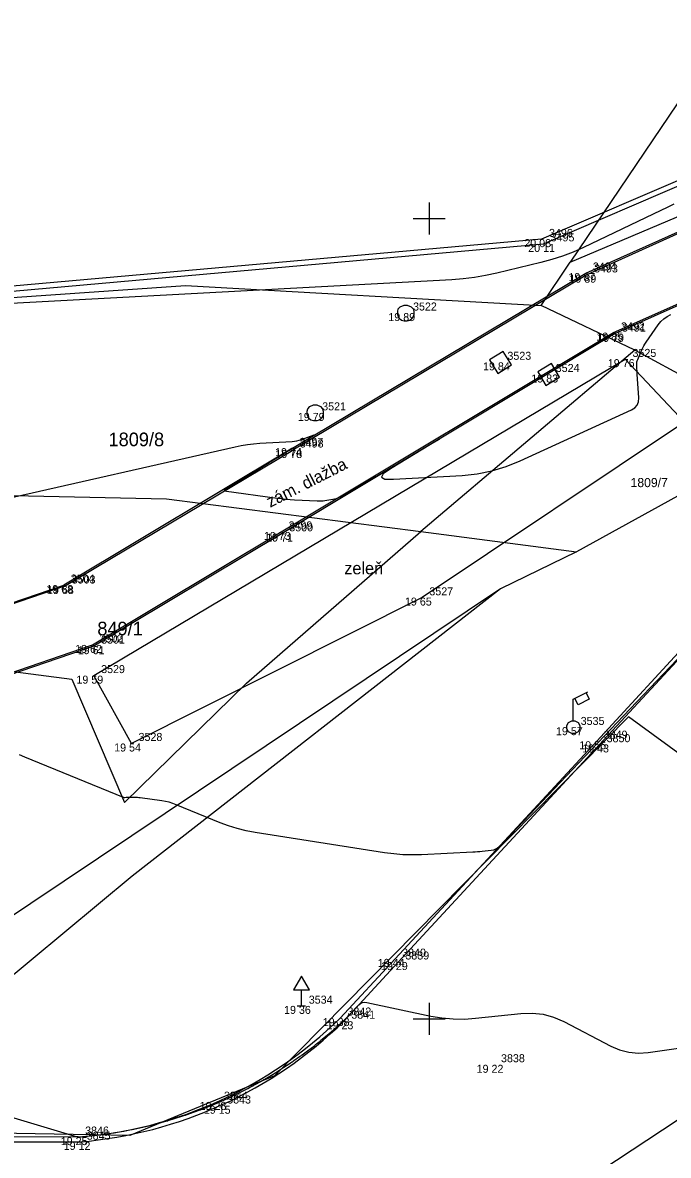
# Model space of a CAD drawing. Extents: x -702257 to -701487, y -1009871 to -1008841.
# Drawn here: x -702162.7 to -702142.52, y -1009729.27 to -1009693.87 of the extents above; entities that cross this region are included whole.
import ezdxf

# ---------------------------------------------------------------- set-up
doc = ezdxf.new("R2010")
doc.units = 0
for name, color, linetype in [('Ex_Major Contours', 7, 'Continuous'), ('Ex_Minor Contours', 7, 'Continuous'), ('Z_body', 7, 'Continuous'), ('Z_body_cisla', 7, 'Continuous'), ('Z_body_vysky_redukovane', 7, 'Continuous'), ('Z_dopravni_znacky', 7, 'Continuous'), ('Z_hektometricka_sit', 7, 'Continuous'), ('Z_katastr_cisla_pozemkova', 7, 'Continuous'), ('Z_katastr_hranice', 7, 'Continuous'), ('Z_komunikace', 7, 'Continuous'), ('Z_obruba', 7, 'Continuous'), ('Z_popisy', 7, 'Continuous'), ('Z_site_kanalizace_znaky', 7, 'Continuous'), ('Z_site_nerozlisene_znaky', 7, 'Continuous'), ('Z_site_vo_znaky', 7, 'Continuous'), ('Z_zelen_obvod', 7, 'Continuous')]:
    doc.layers.add(name, color=color, linetype=linetype)

# ---------------------------------------------------------------- blocks, each defined once
blk = doc.blocks.new('POINT_DISPLAY')
blk.add_line((0, 0), (0, 0))
blk = doc.blocks.new('Z620')
for p, q in [((-0.25, 0.05), (-0.23, 0.13)), ((-0.25, -0.05), (-0.25, 0.05)), ((-0.23, 0.13), (-0.17, 0.2)), ((-0.17, 0.2), (-0.05, 0.25)), ((-0.05, 0.25), (0.05, 0.25)), ((0.05, 0.25), (0.17, 0.2)), ((0.17, 0.2), (0.23, 0.13)), ((0.23, 0.13), (0.25, 0.05)), ((0.25, 0.05), (0.25, -0.05)), ((-0.2, -0.17), (-0.25, -0.05)), ((-0.13, -0.23), (-0.2, -0.17)), ((-0.05, -0.25), (-0.13, -0.23)), ((0.05, -0.25), (-0.05, -0.25)), ((0.13, -0.23), (0.05, -0.25)), ((0.2, -0.17), (0.13, -0.23)), ((0.25, -0.05), (0.2, -0.17))]:
    blk.add_line(p, q)
blk = doc.blocks.new('Z13')
for p, q in [((0, 0.88), (0.45, 1.1)), ((0.4, 1.07), (0.5, 0.88)), ((0, 0.2), (0, 0.88)), ((0.15, 0.7), (0.05, 0.9)), ((0.5, 0.88), (0.15, 0.7)), ((-0.2, 0.05), (-0.15, 0.15)), ((-0.2, -0.05), (-0.2, 0.05)), ((-0.15, 0.15), (-0.05, 0.2)), ((-0.05, 0.2), (0.05, 0.2)), ((0.05, 0.2), (0.15, 0.15)), ((0.15, 0.15), (0.2, 0.05)), ((0.2, 0.05), (0.2, -0.05)), ((-0.15, -0.15), (-0.2, -0.05)), ((-0.05, -0.2), (-0.15, -0.15)), ((0.05, -0.2), (-0.05, -0.2)), ((0.15, -0.15), (0.05, -0.2)), ((0.2, -0.05), (0.15, -0.15))]:
    blk.add_line(p, q)
blk = doc.blocks.new('Z608')
for p, q in [((0.25, 0.25), (-0.25, 0.25)), ((-0.25, 0.25), (-0.25, -0.25)), ((0.25, -0.25), (0.25, 0.25)), ((-0.25, -0.25), (0.25, -0.25))]:
    blk.add_line(p, q)
blk = doc.blocks.new('Z527')
for p, q in [((0, 0.93), (-0.25, 0.5)), ((0.25, 0.5), (0, 0.93)), ((-0.25, 0.5), (0.25, 0.5)), ((0, 0), (0, 0.5)), ((-0.13, 0), (0.13, 0))]:
    blk.add_line(p, q)

msp = doc.modelspace()

# ---------------------------------------------------------------- linework, layer by layer
at = {"layer": 'Ex_Major Contours'}
msp.add_lwpolyline([(-702142.349, -1009699.552), (-702142.555, -1009699.647), (-702142.759, -1009699.744), (-702145.175, -1009700.901), (-702145.498, -1009701.045), (-702145.827, -1009701.172), (-702146.163, -1009701.281), (-702146.505, -1009701.373), (-702147.885, -1009701.704), (-702148.231, -1009701.779), (-702148.58, -1009701.838), (-702148.93, -1009701.881), (-702149.284, -1009701.908), (-702165.593, -1009702.79)], dxfattribs=at)
at = {"layer": 'Ex_Minor Contours'}
for points in [[(-702163.525, -1009708.813), (-702156.058, -1009707.129), (-702155.868, -1009707.09), (-702155.677, -1009707.059), (-702155.485, -1009707.036), (-702155.291, -1009707.02), (-702154.277, -1009706.959), (-702154.203, -1009706.952), (-702154.13, -1009706.94), (-702154.058, -1009706.922), (-702153.987, -1009706.9), (-702153.59, -1009706.758), (-702153.581, -1009706.755), (-702153.577, -1009706.755), (-702153.579, -1009706.758), (-702153.588, -1009706.764), (-702153.634, -1009706.794), (-702153.657, -1009706.809), (-702153.68, -1009706.823), (-702154.115, -1009707.091), (-702154.191, -1009707.138), (-702154.268, -1009707.185), (-702154.344, -1009707.232), (-702154.42, -1009707.279), (-702156.406, -1009708.495), (-702156.407, -1009708.496), (-702156.407, -1009708.498), (-702156.403, -1009708.504), (-702156.401, -1009708.505), (-702156.399, -1009708.505), (-702154.749, -1009708.729), (-702154.613, -1009708.746), (-702154.475, -1009708.761), (-702154.338, -1009708.772), (-702154.201, -1009708.781), (-702153.497, -1009708.82), (-702153.436, -1009708.821), (-702153.375, -1009708.82), (-702153.314, -1009708.815), (-702153.253, -1009708.808), (-702153.01, -1009708.77), (-702152.95, -1009708.758), (-702152.892, -1009708.741), (-702152.836, -1009708.719), (-702152.781, -1009708.691), (-702151.945, -1009708.222), (-702151.788, -1009708.133), (-702151.631, -1009708.044), (-702151.475, -1009707.953), (-702151.32, -1009707.862), (-702149.954, -1009707.051), (-702149.744, -1009706.927), (-702149.674, -1009706.887), (-702149.743, -1009706.93), (-702149.951, -1009707.056), (-702151.209, -1009707.818), (-702151.429, -1009707.975), (-702151.486, -1009708.082), (-702151.379, -1009708.138), (-702151.108, -1009708.143), (-702148.965, -1009708.022), (-702148.496, -1009707.973), (-702148.037, -1009707.882), (-702147.589, -1009707.748), (-702147.151, -1009707.571), (-702143.672, -1009705.976), (-702143.566, -1009705.91), (-702143.493, -1009705.824), (-702143.452, -1009705.719), (-702143.444, -1009705.594), (-702143.493, -1009704.861), (-702143.495, -1009704.823), (-702143.497, -1009704.784), (-702143.499, -1009704.745), (-702143.501, -1009704.707), (-702143.506, -1009704.552), (-702143.505, -1009704.514), (-702143.5, -1009704.477), (-702143.491, -1009704.44), (-702143.478, -1009704.404), (-702143.345, -1009704.098), (-702143.316, -1009704.036), (-702143.284, -1009703.976), (-702143.25, -1009703.917), (-702143.212, -1009703.86), (-702142.837, -1009703.316), (-702142.755, -1009703.214), (-702142.662, -1009703.126), (-702142.557, -1009703.052), (-702142.441, -1009702.993)], [(-702140.79, -1009712.24), (-702143.921, -1009715.537), (-702144.32, -1009715.956), (-702144.719, -1009716.376), (-702145.117, -1009716.795), (-702145.516, -1009717.215), (-702147.81, -1009719.625), (-702147.863, -1009719.672), (-702147.921, -1009719.707), (-702147.985, -1009719.732), (-702148.055, -1009719.745), (-702148.344, -1009719.774), (-702148.417, -1009719.781), (-702148.489, -1009719.787), (-702148.562, -1009719.792), (-702148.635, -1009719.796), (-702150.235, -1009719.875), (-702150.526, -1009719.882), (-702150.816, -1009719.875), (-702151.105, -1009719.852), (-702151.393, -1009719.814), (-702155.439, -1009719.18), (-702155.719, -1009719.128), (-702155.995, -1009719.06), (-702156.266, -1009718.975), (-702156.533, -1009718.875), (-702157.902, -1009718.312), (-702158.012, -1009718.271), (-702158.124, -1009718.237), (-702158.238, -1009718.21), (-702158.354, -1009718.191), (-702159.033, -1009718.1), (-702159.054, -1009718.097), (-702159.075, -1009718.095), (-702159.118, -1009718.091), (-702159.128, -1009718.09), (-702159.138, -1009718.089), (-702159.148, -1009718.088), (-702159.158, -1009718.088), (-702159.199, -1009718.085), (-702159.219, -1009718.084), (-702159.239, -1009718.084), (-702159.278, -1009718.083), (-702159.298, -1009718.083), (-702159.317, -1009718.083), (-702159.356, -1009718.084), (-702159.376, -1009718.084), (-702159.395, -1009718.085), (-702159.434, -1009718.088), (-702159.453, -1009718.089), (-702159.472, -1009718.091), (-702159.511, -1009718.095), (-702159.521, -1009718.095), (-702159.53, -1009718.094), (-702159.539, -1009718.092), (-702159.548, -1009718.089), (-702162.631, -1009716.824), (-702162.806, -1009716.754)], [(-702165.149, -1009727.447), (-702161.105, -1009728.659), (-702161.037, -1009728.676), (-702160.969, -1009728.686), (-702160.899, -1009728.69), (-702160.83, -1009728.686), (-702160.408, -1009728.644), (-702159.85, -1009728.566), (-702159.844, -1009728.565), (-702159.299, -1009728.466), (-702159.279, -1009728.462), (-702158.758, -1009728.344), (-702158.725, -1009728.337), (-702158.715, -1009728.334), (-702158.223, -1009728.202), (-702158.2, -1009728.195), (-702158.17, -1009728.187), (-702158.158, -1009728.184), (-702158.152, -1009728.182), (-702157.698, -1009728.039), (-702157.664, -1009728.028), (-702157.629, -1009728.017), (-702157.611, -1009728.011), (-702157.594, -1009728.005), (-702157.184, -1009727.857), (-702157.148, -1009727.844), (-702157.088, -1009727.822), (-702157.076, -1009727.817), (-702157.065, -1009727.813), (-702157.053, -1009727.808), (-702157.041, -1009727.804), (-702156.742, -1009727.682), (-702156.711, -1009727.67), (-702156.681, -1009727.657), (-702156.607, -1009727.626), (-702156.583, -1009727.616), (-702156.542, -1009727.599), (-702156.526, -1009727.592), (-702156.51, -1009727.584), (-702156.189, -1009727.437), (-702156.15, -1009727.419), (-702156.112, -1009727.401), (-702156.035, -1009727.365), (-702156.016, -1009727.356), (-702155.997, -1009727.347), (-702155.978, -1009727.338), (-702155.959, -1009727.328), (-702155.709, -1009727.2), (-702155.663, -1009727.176), (-702155.617, -1009727.153), (-702155.525, -1009727.105), (-702155.502, -1009727.093), (-702155.479, -1009727.081), (-702155.456, -1009727.068), (-702155.434, -1009727.055), (-702155.242, -1009726.947), (-702155.215, -1009726.932), (-702155.188, -1009726.916), (-702155.161, -1009726.901), (-702155.134, -1009726.886), (-702155.027, -1009726.824), (-702155, -1009726.808), (-702154.974, -1009726.793), (-702154.947, -1009726.777), (-702154.921, -1009726.76), (-702154.787, -1009726.677), (-702154.757, -1009726.658), (-702154.726, -1009726.639), (-702154.695, -1009726.62), (-702154.665, -1009726.6), (-702154.534, -1009726.518), (-702154.508, -1009726.501), (-702154.482, -1009726.484), (-702154.456, -1009726.467), (-702154.43, -1009726.45), (-702154.328, -1009726.38), (-702154.303, -1009726.363), (-702154.278, -1009726.345), (-702154.252, -1009726.328), (-702154.227, -1009726.31), (-702154.046, -1009726.185), (-702154.026, -1009726.171), (-702154.005, -1009726.156), (-702153.985, -1009726.142), (-702153.964, -1009726.126), (-702153.883, -1009726.066), (-702153.843, -1009726.036), (-702153.803, -1009726.005), (-702153.575, -1009725.834), (-702153.56, -1009725.822), (-702153.544, -1009725.81), (-702153.529, -1009725.798), (-702153.514, -1009725.785), (-702153.438, -1009725.724), (-702153.408, -1009725.699), (-702153.392, -1009725.686), (-702153.123, -1009725.464), (-702153.112, -1009725.455), (-702153.101, -1009725.446), (-702153.091, -1009725.437), (-702153.08, -1009725.428), (-702153.028, -1009725.382), (-702152.997, -1009725.354), (-702152.721, -1009725.107), (-702152.699, -1009725.087), (-702152.677, -1009725.066), (-702152.655, -1009725.045), (-702152.634, -1009725.024), (-702152.55, -1009724.937), (-702152.529, -1009724.916), (-702152.508, -1009724.894), (-702152.487, -1009724.873), (-702152.466, -1009724.851), (-702152.197, -1009724.571), (-702152.142, -1009724.526), (-702152.083, -1009724.498), (-702152.018, -1009724.487), (-702151.947, -1009724.494), (-702149.949, -1009724.917), (-702149.599, -1009724.977), (-702149.249, -1009725.008), (-702148.896, -1009725.012), (-702148.543, -1009724.988), (-702147.126, -1009724.836), (-702146.777, -1009724.823), (-702146.437, -1009724.862), (-702146.107, -1009724.95), (-702145.786, -1009725.09), (-702144.322, -1009725.855), (-702144.042, -1009725.976), (-702143.753, -1009726.05), (-702143.457, -1009726.077), (-702143.152, -1009726.056), (-702141.317, -1009725.798)]]:
    msp.add_lwpolyline(points, dxfattribs=at)
at = {"layer": 'Z_hektometricka_sit'}
for p, q in [((-702150, -1009699.5), (-702150, -1009700.5)), ((-702150.5, -1009700), (-702149.5, -1009700)), ((-702150, -1009724.5), (-702150, -1009725.5)), ((-702150.5, -1009725), (-702149.5, -1009725))]:
    msp.add_line(p, q, dxfattribs=at)
at = {"layer": 'Z_katastr_hranice'}
for p, q in [((-702107.96, -1009645.67), (-702145.59, -1009701.36)), ((-702145.59, -1009701.36), (-702123.76, -1009692.13)), ((-702146.5, -1009702.71), (-702145.59, -1009701.36)), ((-702174.11, -1009703.22), (-702157.61, -1009702.09)), ((-702157.61, -1009702.09), (-702146.5, -1009702.71)), ((-702143.57, -1009704.11), (-702146.5, -1009702.71)), ((-702143.57, -1009704.11), (-702150.26, -1009709.78)), ((-702140, -1009706.05), (-702143.57, -1009704.11)), ((-702135.01, -1009704.69), (-702145.39, -1009710.41)), ((-702165.83, -1009708.58), (-702158.21, -1009708.76)), ((-702158.21, -1009708.76), (-702150.26, -1009709.78)), ((-702155.71, -1009714.51), (-702150.26, -1009709.78)), ((-702150.26, -1009709.78), (-702145.39, -1009710.41)), ((-702145.39, -1009710.41), (-702147.77, -1009711.57)), ((-702147.77, -1009711.57), (-702173.19, -1009728.59)), ((-702147.77, -1009711.57), (-702159.28, -1009720.55)), ((-702165.34, -1009713.84), (-702161.17, -1009714.39)), ((-702161.17, -1009714.39), (-702159.52, -1009718.24)), ((-702159.52, -1009718.24), (-702155.71, -1009714.51)), ((-702143.77, -1009715.57), (-702154.83, -1009726.79)), ((-702136.69, -1009720.73), (-702143.77, -1009715.57)), ((-702159.28, -1009720.55), (-702168.84, -1009728.48)), ((-702146.98, -1009731.29), (-702136.39, -1009724.3)), ((-702154.83, -1009726.79), (-702159.35, -1009728.65)), ((-702159.35, -1009728.65), (-702168.84, -1009728.48))]:
    msp.add_line(p, q, dxfattribs=at)
at = {"layer": 'Z_komunikace'}
for p, q in [((-702144.67, -1009716.43), (-702140.14, -1009711.54)), ((-702144.67, -1009716.43), (-702150.96, -1009723.23)), ((-702150.96, -1009723.23), (-702152.66, -1009725.08)), ((-702165.14, -1009728.85), (-702160.92, -1009728.85))]:
    msp.add_line(p, q, dxfattribs=at)
msp.add_ellipse((-702162.036, -1009715.483), major_axis=(13.405, 0.642), ratio=0.999468, start_param=4.747818, end_param=5.438027, dxfattribs=at)
at = {"layer": 'Z_obruba'}
for p, q in [((-702140.91, -1009698.25), (-702146.48, -1009700.64)), ((-702146.42, -1009700.79), (-702140.87, -1009698.39)), ((-702145.1, -1009701.7), (-702140.37, -1009699.58)), ((-702140.36, -1009699.63), (-702145.07, -1009701.75)), ((-702146.48, -1009700.64), (-702174.07, -1009703.09)), ((-702174.11, -1009703.25), (-702146.42, -1009700.79)), ((-702154.27, -1009707.17), (-702145.1, -1009701.7)), ((-702145.07, -1009701.75), (-702154.26, -1009707.23)), ((-702144.23, -1009703.56), (-702139.58, -1009701.49)), ((-702139.58, -1009701.54), (-702144.2, -1009703.6)), ((-702154.62, -1009709.79), (-702144.23, -1009703.56)), ((-702144.2, -1009703.6), (-702154.59, -1009709.84)), ((-702154.27, -1009707.17), (-702161.42, -1009711.45)), ((-702161.4, -1009711.48), (-702154.26, -1009707.23)), ((-702160.52, -1009713.32), (-702154.62, -1009709.79)), ((-702154.59, -1009709.84), (-702160.48, -1009713.36)), ((-702172.64, -1009715.32), (-702161.42, -1009711.45)), ((-702161.4, -1009711.48), (-702172.63, -1009715.38)), ((-702140.25, -1009711.43), (-702144.76, -1009716.33)), ((-702169.36, -1009716.35), (-702160.52, -1009713.32)), ((-702160.48, -1009713.36), (-702169.35, -1009716.4)), ((-702151.06, -1009723.13), (-702144.76, -1009716.33)), ((-702152.78, -1009724.98), (-702151.06, -1009723.13)), ((-702160.97, -1009728.7), (-702165.13, -1009728.68))]:
    msp.add_line(p, q, dxfattribs=at)
msp.add_ellipse((-702161.98, -1009715.619), major_axis=(13.07, 1.289), ratio=0.998996, start_param=4.691201, end_param=5.390354, dxfattribs=at)
at = {"layer": 'Z_zelen_obvod'}
for p, q in [((-702160.48, -1009714.28), (-702143.87, -1009704.39)), ((-702142.01, -1009706.36), (-702143.87, -1009704.39)), ((-702142.01, -1009706.36), (-702150.21, -1009711.84)), ((-702150.21, -1009711.84), (-702159.3, -1009716.4)), ((-702159.3, -1009716.4), (-702160.48, -1009714.28))]:
    msp.add_line(p, q, dxfattribs=at)

# ---------------------------------------------------------------- block references
at = {"layer": 'Z_body'}
for p in [(-702146.48, -1009700.64), (-702146.42, -1009700.79), (-702145.1, -1009701.7), (-702145.07, -1009701.75), (-702150.73, -1009702.95), (-702144.23, -1009703.56), (-702144.2, -1009703.6), (-702147.77, -1009704.49), (-702143.87, -1009704.39), (-702146.26, -1009704.87), (-702153.56, -1009706.07), (-702154.27, -1009707.17), (-702154.26, -1009707.23), (-702154.62, -1009709.79), (-702154.59, -1009709.84), (-702161.42, -1009711.45), (-702161.4, -1009711.48), (-702150.21, -1009711.84), (-702160.52, -1009713.32), (-702160.48, -1009713.36), (-702160.48, -1009714.28), (-702145.49, -1009715.89), (-702144.76, -1009716.33), (-702159.3, -1009716.4), (-702144.67, -1009716.43), (-702151.06, -1009723.13), (-702150.96, -1009723.23), (-702153.99, -1009724.6), (-702152.78, -1009724.98), (-702152.66, -1009725.08), (-702147.97, -1009726.44), (-702156.63, -1009727.6), (-702156.54, -1009727.72), (-702160.97, -1009728.7), (-702160.92, -1009728.85)]:
    msp.add_blockref('POINT_DISPLAY', p, dxfattribs=at)
at = {"layer": 'Z_dopravni_znacky'}
msp.add_blockref('Z527', (-702153.99, -1009724.6), dxfattribs=at)
at = {"layer": 'Z_site_kanalizace_znaky'}
for p in [(-702150.73, -1009702.95), (-702153.56, -1009706.07)]:
    msp.add_blockref('Z620', p, dxfattribs=at)
at = {"layer": 'Z_site_nerozlisene_znaky'}
for p, rotation in [((-702147.77, -1009704.49), 31.5), ((-702146.26, -1009704.87), 30.599999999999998)]:
    msp.add_blockref('Z608', p, dxfattribs=dict(at, rotation=rotation))
at = {"layer": 'Z_site_vo_znaky'}
msp.add_blockref('Z13', (-702145.49, -1009715.89), dxfattribs=at)

# ---------------------------------------------------------------- texts
at = {"layer": 'Z_body_cisla'}
for s, p in [('3496', (-702146.25, -1009700.57)), ('3495', (-702146.2, -1009700.71)), ('3494', (-702144.88, -1009701.62)), ('3493', (-702144.84, -1009701.68)), ('3522', (-702150.5, -1009702.87)), ('3492', (-702144, -1009703.49)), ('3491', (-702143.97, -1009703.53)), ('3523', (-702147.55, -1009704.41)), ('3525', (-702143.64, -1009704.32)), ('3524', (-702146.04, -1009704.79)), ('3521', (-702153.34, -1009705.99)), ('3497', (-702154.05, -1009707.1)), ('3498', (-702154.04, -1009707.15)), ('3499', (-702154.39, -1009709.71)), ('3500', (-702154.37, -1009709.77)), ('3504', (-702161.2, -1009711.37)), ('3503', (-702161.17, -1009711.4)), ('3527', (-702149.99, -1009711.77)), ('3502', (-702160.3, -1009713.24)), ('3501', (-702160.25, -1009713.28)), ('3529', (-702160.25, -1009714.2)), ('3535', (-702145.26, -1009715.82)), ('3849', (-702144.54, -1009716.25)), ('3528', (-702159.08, -1009716.32)), ('3850', (-702144.45, -1009716.36)), ('3840', (-702150.84, -1009723.06)), ('3839', (-702150.74, -1009723.15)), ('3534', (-702153.76, -1009724.53)), ('3842', (-702152.55, -1009724.9)), ('3841', (-702152.43, -1009725)), ('3838', (-702147.75, -1009726.36)), ('3844', (-702156.41, -1009727.53)), ('3843', (-702156.31, -1009727.65)), ('3846', (-702160.75, -1009728.62)), ('3845', (-702160.7, -1009728.78))]:
    msp.add_text(s, height=0.25, dxfattribs=at).set_placement(p)
at = {"layer": 'Z_body_vysky_redukovane'}
for s, p in [('20 08', (-702147.022, -1009700.89)), ('20 11', (-702146.899, -1009701.04)), ('19 87', (-702145.642, -1009701.95)), ('19 89', (-702145.612, -1009702)), ('19 89', (-702151.272, -1009703.2)), ('19 85', (-702144.772, -1009703.81)), ('19 79', (-702144.742, -1009703.85)), ('19 84', (-702148.312, -1009704.74)), ('19 76', (-702144.412, -1009704.64)), ('19 83', (-702146.802, -1009705.12)), ('19 79', (-702154.102, -1009706.32)), ('19 74', (-702154.812, -1009707.42)), ('19 78', (-702154.802, -1009707.48)), ('19 73', (-702155.162, -1009710.04)), ('19 71', (-702155.09, -1009710.09)), ('19 68', (-702161.962, -1009711.7)), ('19 68', (-702161.942, -1009711.73)), ('19 65', (-702150.752, -1009712.09)), ('19 62', (-702161.062, -1009713.57)), ('19 61', (-702160.98, -1009713.61)), ('19 59', (-702161.022, -1009714.53)), ('19 57', (-702146.032, -1009716.14)), ('19 56', (-702145.302, -1009716.58)), ('19 54', (-702159.842, -1009716.65)), ('19 43', (-702145.212, -1009716.68)), ('19 44', (-702151.602, -1009723.38)), ('19 29', (-702151.502, -1009723.48)), ('19 36', (-702154.532, -1009724.85)), ('19 38', (-702153.322, -1009725.23)), ('19 23', (-702153.202, -1009725.33)), ('19 22', (-702148.512, -1009726.69)), ('19 28', (-702157.172, -1009727.85)), ('19 15', (-702157.04, -1009727.97)), ('19 25', (-702161.512, -1009728.95)), ('19 12', (-702161.42, -1009729.1))]:
    msp.add_text(s, height=0.25, dxfattribs=at).set_placement(p)
at = {"layer": 'Z_katastr_cisla_pozemkova'}
for s, height, p in [('1809/8', 0.425, (-702160.019, -1009707.11)), ('1809/7', 0.285, (-702143.701, -1009708.389)), ('849/1', 0.425, (-702160.369, -1009713.02))]:
    msp.add_text(s, height=height, dxfattribs=at).set_placement(p)
at = {"layer": 'Z_popisy'}
msp.add_text('zám. dlažba', height=0.38, rotation=27, dxfattribs=at).set_placement((-702154.965, -1009709.036))
msp.add_text('zeleň', height=0.38, dxfattribs=at).set_placement((-702152.65, -1009711.113))

doc.saveas('drawing.dxf')
